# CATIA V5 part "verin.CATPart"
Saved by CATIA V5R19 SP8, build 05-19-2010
Part number: verin
Publications: "axeverin", "axeF"
Bounding box of the stored display mesh (mm): x -20 to 20, y 0 to 200, z 0 to 0
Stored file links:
  C:\Users\rcousturie\Desktop\EU_thinkMotion\iao\IAO_MMS_Groupe1\flamrini\Lamrini_projet_IAO2011\Lamrini_projet_IAO2011\projet_iao_traindatterrissage\projet_iao_traindatterrissage\verin.CATPart
  C:\Users\rcousturie\Desktop\EU_thinkMotion\iao\IAO_MMS_Groupe1\flamrini\Lamrini_projet_IAO2011\Lamrini_projet_IAO2011\projet_iao_traindatterrissage\projet_iao_traindatterrissage\squelettetrain.CATProduct
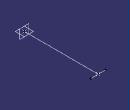
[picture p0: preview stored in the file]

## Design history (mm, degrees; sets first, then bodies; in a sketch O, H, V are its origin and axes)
Set1
  Point1 "PointF": linked copy from another document
  Point2 "PointE": linked copy from another document
Set2 "Set géométrique.5"
  Line1 "axeverin": type PtPt, FirstPoint Point1, SecondPoint Point2
  Line2 "axeF": type PtDir, RefPoint Point1, Direction yz-plane, Start -20, End 20
Body1 (main body)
